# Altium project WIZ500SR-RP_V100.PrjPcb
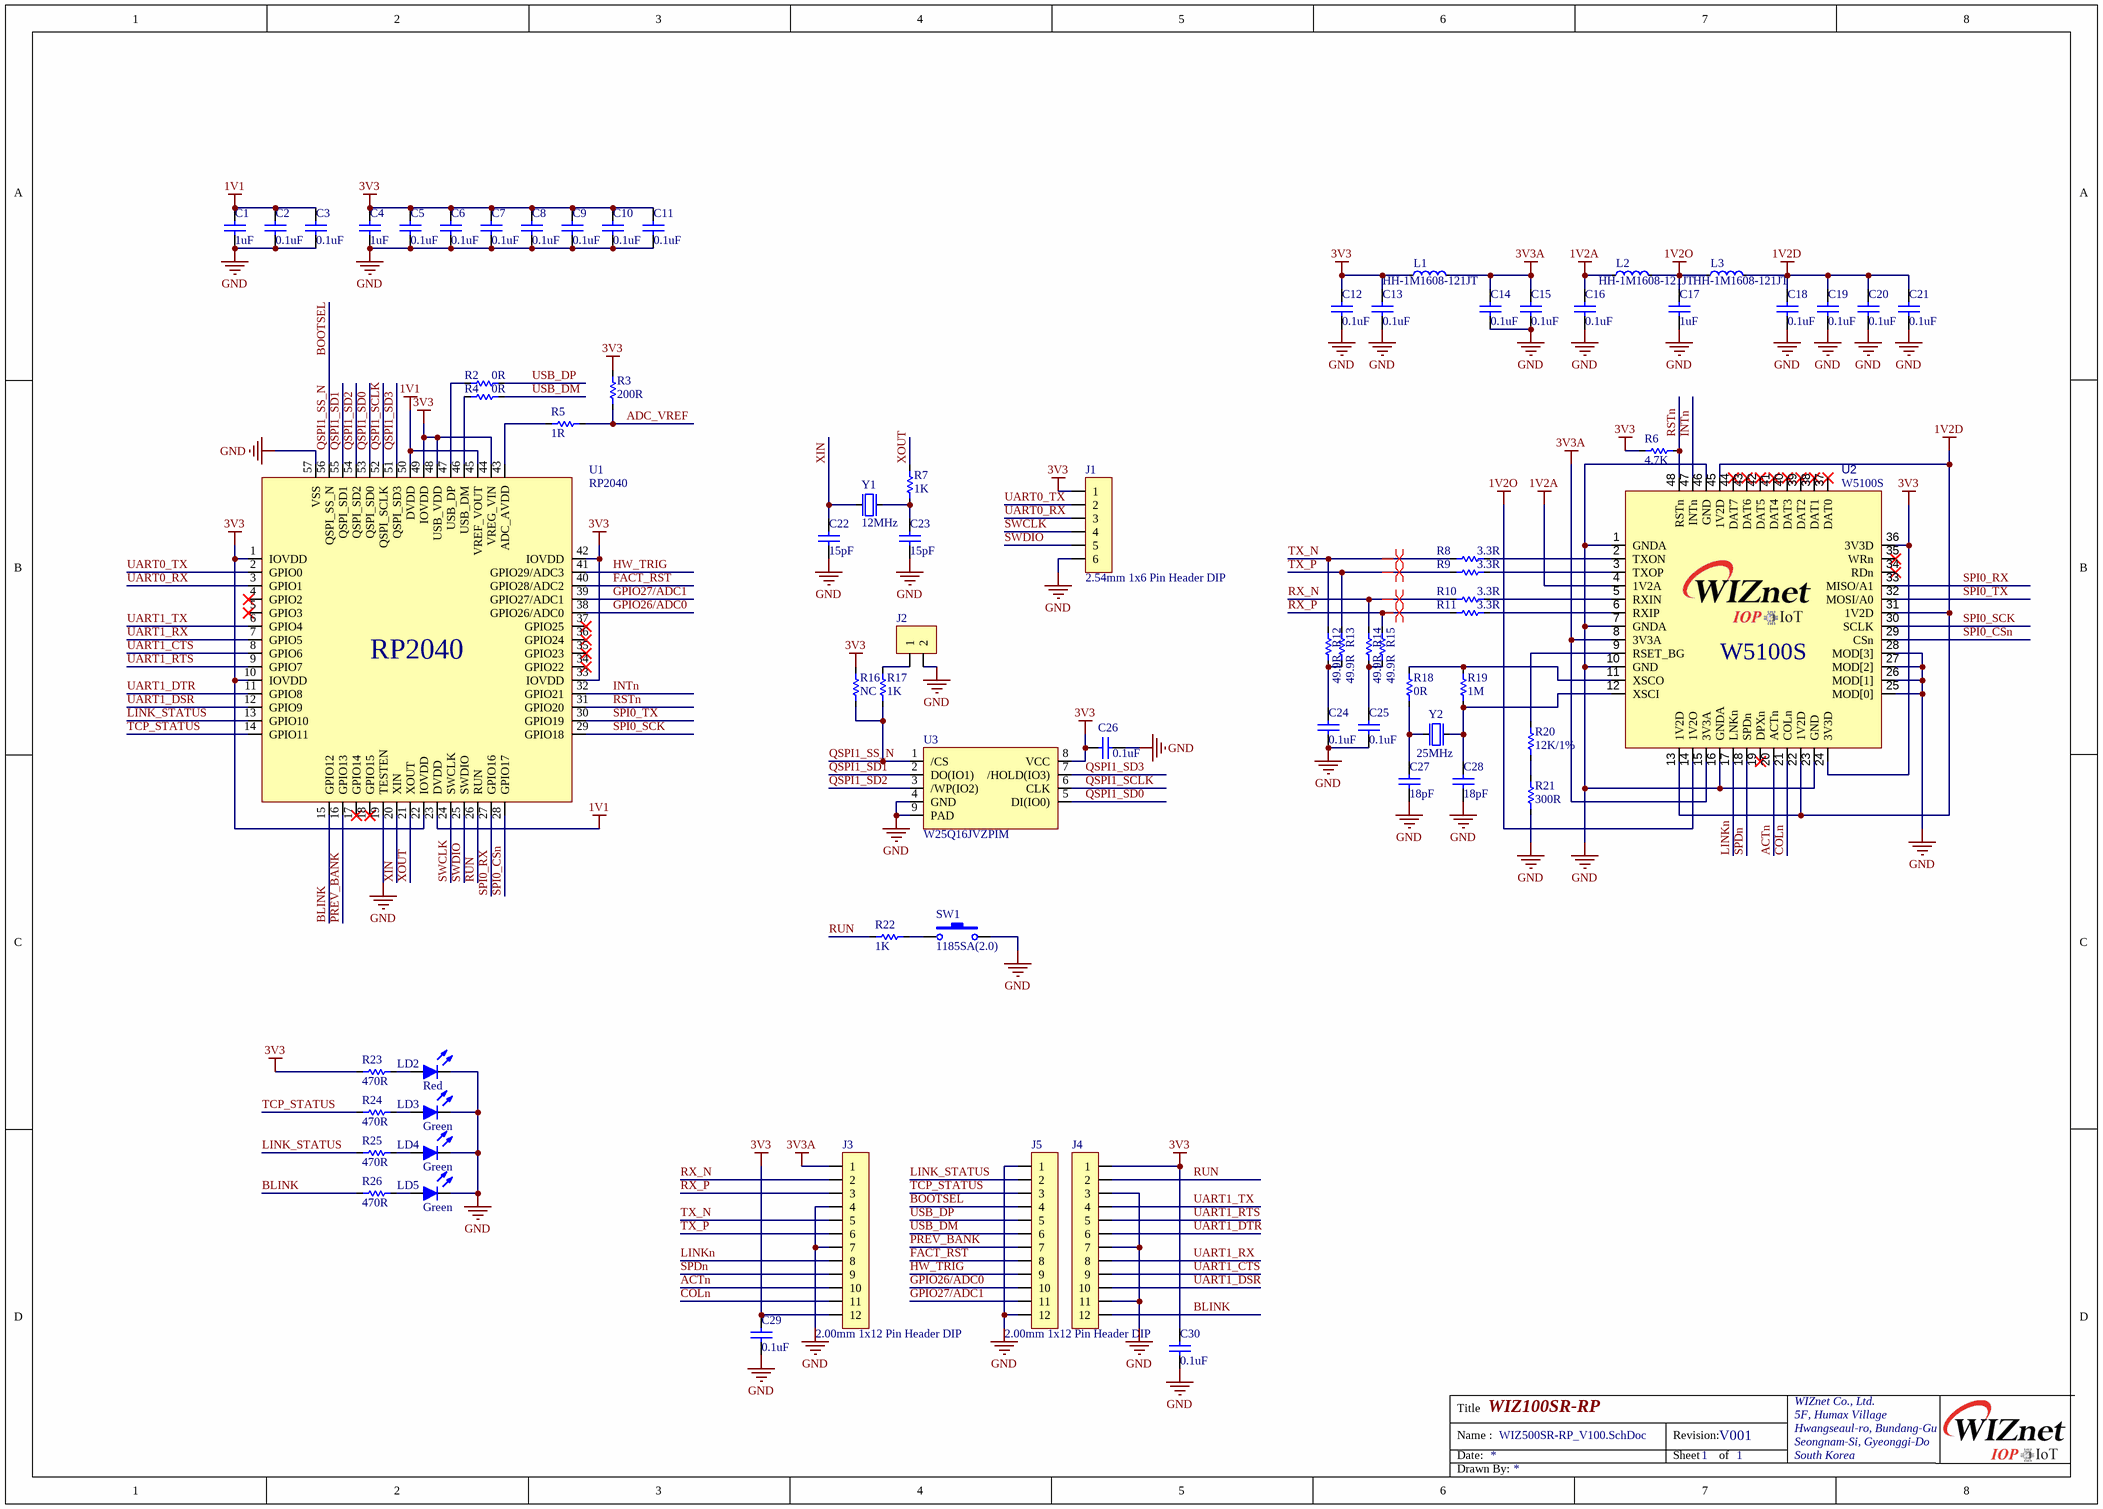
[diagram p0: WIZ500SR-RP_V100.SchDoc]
1 sheet, 73 parts. Net scope: global (net labels, ports and power ports of the same name join across sheets).
Board file: WIZ500SR-RP_V100.PcbDoc

## Sheet WIZ500SR-RP_V100.SchDoc: WIZ100SR-RP
size A3; Organization: WIZnet Co., Ltd.; Address1: 5F, Humax Village; Address2: Hwangseaul-ro, Bundang-Gu; Address3: Seongnam-Si, Gyeonggi-Do; Address4: South Korea; Revision: V001; SheetNumber: 1; SheetTotal: 1

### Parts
C1  1uF  [CAP-0402]
C2  0.1uF  [CAP-0402]
C3  0.1uF  [CAP-0402]
C4  1uF  [CAP-0402]
C5  0.1uF  [CAP-0402]
C6  0.1uF  [CAP-0402]
C7  0.1uF  [CAP-0402]
C8  0.1uF  [CAP-0402]
C9  0.1uF  [CAP-0402]
C10  0.1uF  [CAP-0402]
C11  0.1uF  [CAP-0402]
C12  0.1uF  [CAP-0402]
C13  0.1uF  [CAP-0402]
C14  0.1uF  [CAP-0402]
C15  0.1uF  [CAP-0402]
C16  0.1uF  [CAP-0402]
C17  1uF  [CAP-0402]
C18  0.1uF  [CAP-0402]
C19  0.1uF  [CAP-0402]
C20  0.1uF  [CAP-0402]
C21  0.1uF  [CAP-0402]
C22  15pF  [CAP-0402]
C23  15pF  [CAP-0402]
C24  0.1uF  [CAP-0402]
C25  0.1uF  [CAP-0402]
C26  0.1uF  [CAP-0402]
C27  18pF  [CAP-0402]
C28  18pF  [CAP-0402]
C29  0.1uF  [CAP-0402]
C30  0.1uF  [CAP-0402]
J1  2.54mm 1x6 Pin Header DIP  [IDC-1X6]
J2  2.54mm 1x2 Pin Header DIP  [IDC-1X2]  (value not drawn)
J3  2.00mm 1x12 Pin Header DIP  [IDC-1X12(2MM)]
J4  2.00mm 1x12 Pin Header DIP  [IDC-1X12(2MM)]  (value not drawn)
J5  2.00mm 1x12 Pin Header DIP  [IDC-1X12(2MM)]
L1  HH-1M1608-121JT  [IND-0603]
L2  HH-1M1608-121JT  [IND-0603]
L3  HH-1M1608-121JT  [IND-0603]
LD2  Red  [LED-0603-green]
LD3  Green  [LED-0603-green]
LD4  Green  [LED-0603-green]
LD5  Green  [LED-0603-green]
R2  0R  [RES-0402]
R3  200R  [RES-0402]
R4  0R  [RES-0402]
R5  1R  [RES-0402]
R6  4.7K  [RES-0402]
R7  1K  [RES-0402]
R8  3.3R  [RES-0402]
R9  3.3R  [RES-0402]
R10  3.3R  [RES-0402]
R11  3.3R  [RES-0402]
R12  49.9R  [RES-0402]
R13  49.9R  [RES-0402]
R14  49.9R  [RES-0402]
R15  49.9R  [RES-0402]
R16  NC  [RES-0402]
R17  1K  [RES-0402]
R18  0R  [RES-0402]
R19  1M  [RES-0402]
R20  12K/1%  [RES-0402]
R21  300R  [RES-0402]
R22  1K  [RES-0402]
R23  470R  [RES-0402]
R24  470R  [RES-0402]
R25  470R  [RES-0402]
R26  470R  [RES-0402]
SW1  1185SA(2.0)  [ST-1185S]
U1  RP2040  [RP2040_QFN56(0.4/7X7)]
U2  W5100S  [LQFP48(0.5/9.0)]
U3  W25Q16JVZPIM  [WSON8(6X5_1.27)]
Y1  12MHz  [OSC-TZ1067B]
Y2  25MHz  [OSC-82J0626]

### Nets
1V1: C1.2 C2.2 C3.2 U1.23(DVDD) U1.45(VREF_VOUT) U1.50(DVDD)
1V2A: C16.2 L2.1 U2.4(1V2A)
1V2D: C18.2 C19.2 C20.2 C21.2 L3.2 U2.13(1V2D) U2.22(1V2D) U2.31(1V2D) U2.45(1V2D)
1V2O: C17.2 L2.2 L3.1 U2.14(1V2O)
3V3: C4.2 C5.2 C6.2 C7.2 C8.2 C9.2 C10.2 C11.2 C12.2 C13.2 C26.2 C29.2 C30.2 J1.1 J3.12 J4.1 L1.1 R3.1 R6.1 R16.2 R23.2 U1.1(IOVDD) U1.10(IOVDD) U1.22(IOVDD) U1.33(IOVDD) U1.42(IOVDD) U1.44(VREG_VIN) U1.48(USB_VDD) U1.49(IOVDD) U2.24(3V3D) U2.36(3V3D) U3.8(VCC)
3V3A: C14.2 C15.2 J3.1 L1.2 U2.8(3V3A) U2.15(3V3A)
GND: C1.1 C2.1 C3.1 C4.1 C5.1 C6.1 C7.1 C8.1 C9.1 C10.1 C11.1 C12.1 C13.1 C14.1 C15.1 C16.1 C17.1 C18.1 C19.1 C20.1 C21.1 C22.2 C23.2 C24.1 C25.1 C26.1 C27.1 C28.1 C29.1 C30.1 J1.6 J2.2 J3.4 J3.7 J4.3 J4.7 J4.11 J5.1 J5.12 LD2.2(K) LD3.2(K) LD4.2(K) LD5.2(K) R21.2 SW1.2 U1.19(TESTEN) U1.57(VSS) U2.1(GNDA) U2.7(GNDA) U2.10(GND) U2.16(GNDA) U2.23(GND) U2.25(MOD[0]) U2.26(MOD[1]) U2.27(MOD[2]) U2.28(MOD[3]) U2.46(GND) U3.4(GND) U3.9(PAD) Y1.2 Y1.4 Y2.2(GND) Y2.4(GND)
ACTn: J3.10 U2.20(ACTn)
ADC_VREF: R3.2 R5.2
BLINK: J4.12 R26.2 U1.15(GPIO12)
BOOTSEL: J5.4 R16.1 R17.1 U1.56(QSPI_SS_N) U3.1(/CS)  [also labelled QSPI1_SS_N]
COLn: J3.11 U2.21(COLn)
FACT_RST: J5.8 U1.40(GPIO28/ADC2)
GPIO26/ADC0: J5.10 U1.38(GPIO26/ADC0)
GPIO27/ADC1: J5.11 U1.39(GPIO27/ADC1)
HW_TRIG: J5.9 U1.41(GPIO29/ADC3)
INTn: U1.32(GPIO21) U2.47(INTn)
LINK_STATUS: J5.2 R25.2 U1.13(GPIO10)
LINKn: J3.8 U2.17(LNKn)
PREV_BANK: J5.7 U1.16(GPIO13)
QSPI1_SCLK: U1.52(QSPI_SCLK) U3.6(CLK)
QSPI1_SD0: U1.53(QSPI_SD0) U3.5(DI(IO0))
QSPI1_SD1: U1.55(QSPI_SD1) U3.2(DO(IO1))
QSPI1_SD2: U1.54(QSPI_SD2) U3.3(/WP(IO2))
QSPI1_SD3: U1.51(QSPI_SD3) U3.7(/HOLD(IO3))
RSTn: R6.2 U1.31(GPIO20) U2.48(RSTn)
RUN: J4.2 R22.2 U1.26(RUN)
RX_N: J3.2 R10.1 R14.2
RX_P: J3.3 R11.1 R15.2
SPDn: J3.9 U2.18(SPDn)
SPI0_CSn: U1.28(GPIO17) U2.29(CSn)
SPI0_RX: U1.27(GPIO16) U2.33(MISO/A1)
SPI0_SCK: U1.29(GPIO18) U2.30(SCLK)
SPI0_TX: U1.30(GPIO19) U2.32(MOSI/A0)
SWCLK: J1.4 U1.24(SWCLK)
SWDIO: J1.5 U1.25(SWDIO)
TCP_STATUS: J5.3 R24.2 U1.14(GPIO11)
TX_N: J3.5 R8.1 R12.2
TX_P: J3.6 R9.1 R13.2
UART0_RX: J1.3 U1.3(GPIO1)
UART0_TX: J1.2 U1.2(GPIO0)
UART1_CTS: J4.9 U1.8(GPIO6)
UART1_DSR: J4.10 U1.12(GPIO9)
UART1_DTR: J4.6 U1.11(GPIO8)
UART1_RTS: J4.5 U1.9(GPIO7)
UART1_RX: J4.8 U1.7(GPIO5)
UART1_TX: J4.4 U1.6(GPIO4)
USB_DM: J5.6 R4.1
USB_DP: J5.5 R2.1
XIN: C22.1 U1.20(XIN) Y1.1(inp)
XOUT: R7.2 U1.21(XOUT)
NetC23_1: C23.1 R7.1 Y1.3(out)
NetC24_2: C24.2 R12.1 R13.1
NetC25_2: C25.2 R14.1 R15.1
NetC27_2: C27.2 R18.1 Y2.1(inp)
NetC28_2: C28.2 R19.1 U2.12(XSCI) Y2.3(out)
NetJ2_1: J2.1 R17.2
NetLD2_1: LD2.1(A) R23.1
NetLD3_1: LD3.1(A) R24.1
NetLD4_1: LD4.1(A) R25.1
NetLD5_1: LD5.1(A) R26.1
NetR2_2: R2.2 U1.47(USB_DP)
NetR4_2: R4.2 U1.46(USB_DM)
NetR5_1: R5.1 U1.43(ADC_AVDD)
NetR8_2: R8.2 U2.2(TXON)
NetR9_2: R9.2 U2.3(TXOP)
NetR10_2: R10.2 U2.5(RXIN)
NetR11_2: R11.2 U2.6(RXIP)
NetR18_2: R18.2 R19.2 U2.11(XSCO)
NetR20_1: R20.1 U2.9(RSET_BG)
NetR20_2: R20.2 R21.1
NetR22_1: R22.1 SW1.1

Not connected (* = marked no-connect by the designer): U1 4(GPIO2)* 5(GPIO3)* 17(GPIO14)* 18(GPIO15)* 34(GPIO22)* 35(GPIO23)* 36(GPIO24)* 37(GPIO25)*; U2 19(DPXn)* 34(RDn)* 35(WRn)* 37(DAT0)* 38(DAT1)* 39(DAT2)* 40(DAT3)* 41(DAT4)* 42(DAT5)* 43(DAT6)* 44(DAT7)*

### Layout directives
differential pair: RX_N, RX_P, TX_N, TX_P

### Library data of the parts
C1-C30 = CAP-0402: Ceramic CAP 0402(1005)
L1-L3 = IND-0603: Inductor 0603(1608)
LD2-LD5 = LED-0603
R2-R26 = RES-0402
SW1 = ITS-1107(SMD): TACT Switch (SMD)
U1 = RP2040: Raspverry Pi, Dual ARM Cortex-M0+ @ 133MHz
U2 = W5100S: WIZnet Hardwired TCP/IP Chip
U3 = W25Q16JVZPIM: 3V 16M-BIT / SERIAL FLASH MEMORY WITH / DUAL/QUAD SPI, QPI & DTR
Y1 = OSC-TZ1067B-12MHz: X-tal 12MHz,3.2x2.5 SMD, CL=20pF
Y2 = OSC-82J0626-25MHz: X-tal 25MHz,3.2x2.5 SMD, CL=18pF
